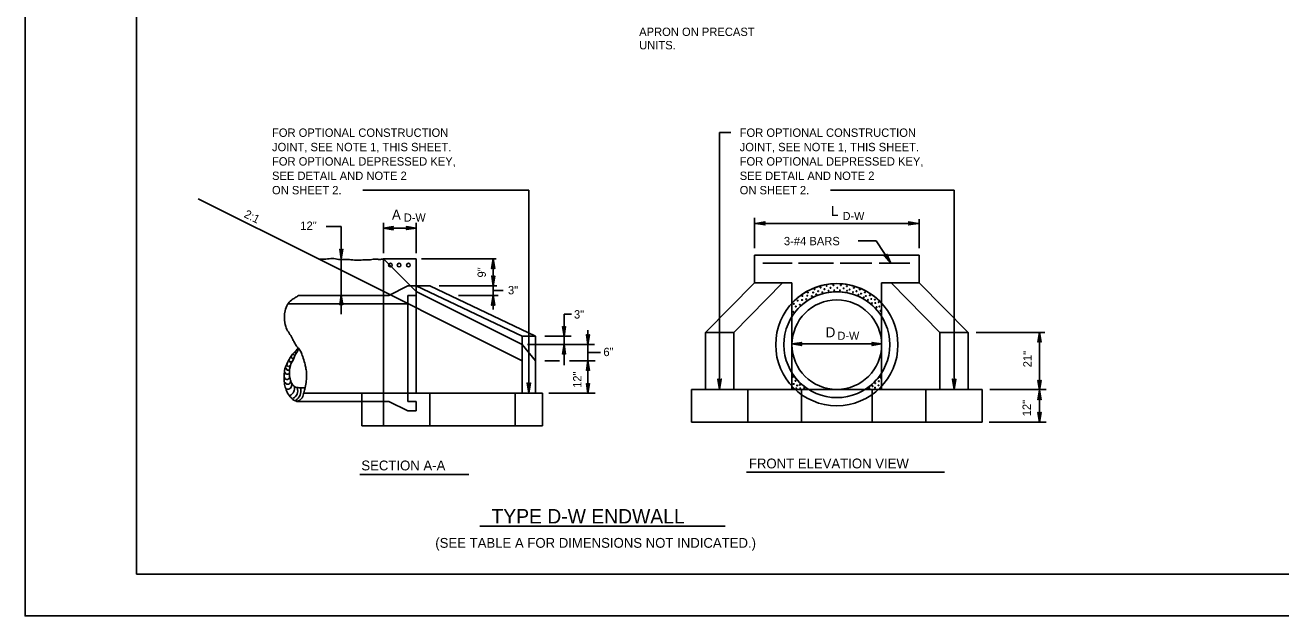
# Model space of a CAD drawing. Extents: x 638877 to 639960, y 297341 to 299123.
# Drawn here: x 638877.2 to 639328, y 297341.3 to 297553.4 of the extents above; entities that cross this region are included whole.
import ezdxf

# ---------------------------------------------------------------- set-up
doc = ezdxf.new("R2010")
doc.units = 0
for name, color, linetype in [('1', 7, 'Continuous'), ('2', 7, 'Continuous'), ('3', 7, 'Continuous'), ('PLT-BNDY', 7, 'Continuous')]:
    doc.layers.add(name, color=color, linetype=linetype)

msp = doc.modelspace()

# ---------------------------------------------------------------- linework, layer by layer
at = {"layer": '1'}
for p, q in [((638917.19, 297920.28), (638917.19, 297356.28)), ((638917.19, 297356.28), (639703.19, 297356.28))]:
    msp.add_line(p, q, dxfattribs=at)
for centre in [(639008.35, 297467.27), (639011.45, 297467.27), (639014.81, 297467.27)]:
    msp.add_circle(centre, 0.66, dxfattribs=at)
at = {"layer": '2'}
for p, q in [((639126.51, 297422.58), (639126.51, 297514.89)), ((639126.51, 297514.89), (639130.58, 297514.89)), ((639058.02, 297494.17), (638998.4, 297494.17)), ((639058.02, 297421.23), (639058.02, 297494.17)), ((639166.3, 297494.12), (639210.67, 297494.12)), ((639210.67, 297422.58), (639210.67, 297494.12)), ((638982.47, 297469.49), (638939.33, 297491.06)), ((638990.69, 297481.06), (638985.3, 297481.06)), ((638990.69, 297469.49), (638990.69, 297481.06)), ((639005.87, 297471.49), (639005.87, 297482.49)), ((639017.57, 297480.53), (639005.87, 297480.53)), ((639017.57, 297471.49), (639017.57, 297482.49)), ((639138.99, 297484.19), (639138.99, 297473.28)), ((639197.84, 297482.24), (639139.34, 297482.24)), ((639198.18, 297483.73), (639198.18, 297473.28)), ((639182.69, 297475.98), (639176.23, 297475.98)), ((639182.69, 297475.98), (639188.03, 297467.96)), ((639198.18, 297470.84), (639138.99, 297470.84)), ((639138.99, 297470.84), (639138.99, 297460.91)), ((639198.18, 297470.84), (639198.18, 297460.91)), ((639055.58, 297432.93), (638982.47, 297469.49)), ((638990.69, 297456.46), (638990.69, 297469.49)), ((639005.87, 297469.49), (639005.87, 297409.53)), ((639017.57, 297469.49), (639005.87, 297469.49)), ((639017.57, 297457.78), (639005.87, 297469.49)), ((639017.57, 297469.49), (639017.57, 297421.23)), ((639046.25, 297469.49), (639019.46, 297469.49)), ((639045.24, 297459.8), (639045.24, 297469.49)), ((639152.61, 297467.91), (639141.99, 297467.91)), ((639167.39, 297467.91), (639154.8, 297467.91)), ((639181.21, 297467.91), (639169.79, 297467.91)), ((639194.78, 297467.91), (639183.79, 297467.91)), ((639007.79, 297456.33), (639014.64, 297459.76)), ((639017.57, 297459.76), (639014.64, 297459.76)), ((639055.58, 297441.71), (639017.57, 297459.76)), ((639022.44, 297459.76), (639017.57, 297459.76)), ((639055.58, 297438.78), (639017.57, 297457.78)), ((639060.46, 297441.71), (639022.44, 297459.76)), ((639046.58, 297459.8), (639025.81, 297459.8)), ((639045.24, 297451.32), (639045.24, 297459.8)), ((639048.82, 297458.16), (639045.24, 297458.16)), ((639138.99, 297460.91), (639121.44, 297443.06)), ((639149.07, 297460.85), (639131.58, 297443.06)), ((639152.5, 297460.91), (639138.99, 297460.91)), ((639152.5, 297460.91), (639152.5, 297422.58)), ((639184.67, 297460.91), (639184.67, 297422.58)), ((639198.18, 297460.91), (639184.67, 297460.91)), ((639205.6, 297443.06), (639188.1, 297460.85)), ((639215.73, 297443.06), (639198.18, 297460.91)), ((639014.64, 297453.4), (638971.88, 297453.4)), ((639004.71, 297456.33), (638975.28, 297456.33)), ((638990.69, 297449.67), (638990.69, 297456.46)), ((639007.79, 297456.33), (639004.71, 297456.33)), ((639014.64, 297456.33), (639014.64, 297418.3)), ((639017.57, 297456.33), (639014.64, 297456.33)), ((639047.07, 297456.33), (639032.78, 297456.33)), ((639073.32, 297449.66), (639070.66, 297449.66)), ((639070.66, 297441.71), (639070.66, 297449.66)), ((639079.24, 297441.71), (639079.24, 297443.86)), ((639055.58, 297441.71), (639055.58, 297421.23)), ((639060.46, 297441.71), (639055.58, 297441.71)), ((639060.46, 297441.71), (639060.46, 297421.23)), ((639073.27, 297441.71), (639063.78, 297441.71)), ((639070.66, 297431.32), (639070.66, 297441.71)), ((639079.24, 297432.93), (639079.24, 297441.71)), ((639131.58, 297443.06), (639121.44, 297443.06)), ((639121.44, 297422.58), (639121.44, 297443.06)), ((639131.58, 297422.58), (639131.58, 297443.06)), ((639215.73, 297443.06), (639205.6, 297443.06)), ((639205.6, 297422.58), (639205.6, 297443.06)), ((639215.73, 297422.58), (639215.73, 297443.06)), ((639243.3, 297443.06), (639218.63, 297443.06)), ((639241.36, 297443.06), (639241.36, 297422.37)), ((639055.58, 297438.78), (639060.46, 297432.93)), ((639081.55, 297438.78), (639057.51, 297438.78)), ((639083.74, 297435.84), (639079.43, 297435.84)), ((639184.67, 297438.95), (639152.5, 297438.95)), ((639069.07, 297432.93), (639063.73, 297432.93)), ((639081.78, 297432.93), (639072.59, 297432.93)), ((639079.24, 297421.23), (639079.24, 297432.93)), ((638998.07, 297421.23), (638977.24, 297421.23)), ((638998.07, 297421.23), (638998.07, 297409.53)), ((639055.58, 297421.23), (638998.07, 297421.23)), ((639022.45, 297421.23), (639022.45, 297409.53)), ((639053.15, 297421.23), (639053.15, 297409.53)), ((639055.58, 297421.23), (639060.46, 297421.23)), ((639062.9, 297421.23), (639060.46, 297421.23)), ((639062.9, 297421.23), (639062.9, 297409.53)), ((639081.78, 297421.23), (639065.15, 297421.23)), ((639116.38, 297410.88), (639116.38, 297422.58)), ((639121.44, 297422.58), (639116.38, 297422.58)), ((639131.58, 297422.58), (639121.44, 297422.58)), ((639205.6, 297422.58), (639131.58, 297422.58)), ((639136.64, 297410.88), (639136.64, 297422.58)), ((639155.88, 297410.88), (639155.88, 297422.58)), ((639168.59, 297422.58), (639168.59, 297422.58)), ((639181.3, 297410.88), (639181.3, 297422.58)), ((639200.54, 297410.88), (639200.54, 297422.58)), ((639215.74, 297422.58), (639205.6, 297422.58)), ((639220.8, 297422.58), (639215.73, 297422.58)), ((639220.8, 297410.88), (639220.8, 297422.58)), ((639243.73, 297422.58), (639223.54, 297422.58)), ((639241.36, 297422.37), (639241.36, 297410.88)), ((638998.07, 297418.3), (638974.56, 297418.3)), ((639007.79, 297418.3), (638998.07, 297418.3)), ((639014.64, 297414.88), (639007.79, 297418.3)), ((639017.57, 297418.3), (639014.64, 297418.3)), ((639017.57, 297418.3), (639017.57, 297414.88)), ((639017.57, 297414.88), (639014.64, 297414.88)), ((639062.9, 297409.53), (638998.07, 297409.53)), ((639220.8, 297410.88), (639116.38, 297410.88)), ((639243.73, 297410.88), (639223.32, 297410.88))]:
    msp.add_line(p, q, dxfattribs=at)
for points in [[(639009.17, 297480.11), (639009.05, 297480.35), (639005.87, 297480.53), (639009.17, 297480.11), (639009.35, 297479.97), (639005.87, 297480.53), (639009.05, 297480.69), (639009.17, 297480.93), (639005.87, 297480.53), (639009.35, 297481.08), (639009.17, 297480.93)], [(639014.27, 297480.95), (639014.39, 297480.71), (639017.57, 297480.53), (639014.27, 297480.95), (639014.09, 297481.09), (639017.57, 297480.53), (639014.39, 297480.37), (639014.27, 297480.14), (639017.57, 297480.53), (639014.09, 297479.98), (639014.27, 297480.14)], [(639142.64, 297481.82), (639142.52, 297482.06), (639139.34, 297482.24), (639142.64, 297481.82), (639142.81, 297481.68), (639139.34, 297482.24), (639142.52, 297482.39), (639142.63, 297482.63), (639139.34, 297482.24), (639142.81, 297482.79), (639142.63, 297482.63)], [(639194.53, 297482.65), (639194.65, 297482.41), (639197.84, 297482.24), (639194.53, 297482.65), (639194.36, 297482.79), (639197.84, 297482.24), (639194.66, 297482.08), (639194.54, 297481.84), (639197.84, 297482.24), (639194.36, 297481.68), (639194.54, 297481.84)], [(638991.11, 297472.79), (638990.87, 297472.67), (638990.69, 297469.49), (638991.11, 297472.79), (638991.25, 297472.96), (638990.69, 297469.49), (638990.54, 297472.67), (638990.3, 297472.78), (638990.69, 297469.49), (638990.14, 297472.96), (638990.3, 297472.78)], [(639186.54, 297470.94), (639186.41, 297470.7), (639188.03, 297467.96), (639186.54, 297470.94), (639186.56, 297471.16), (639188.03, 297467.96), (639186.13, 297470.51), (639185.87, 297470.48), (639188.03, 297467.96), (639185.64, 297470.54), (639185.87, 297470.48)], [(639044.82, 297466.18), (639045.06, 297466.31), (639045.24, 297469.49), (639044.82, 297466.18), (639044.68, 297466.01), (639045.24, 297469.49), (639045.4, 297466.31), (639045.63, 297466.19), (639045.24, 297469.49), (639045.79, 297466.01), (639045.63, 297466.19)], [(639045.66, 297463.11), (639045.42, 297462.99), (639045.24, 297459.8), (639045.66, 297463.11), (639045.8, 297463.28), (639045.24, 297459.8), (639045.08, 297462.98), (639044.84, 297463.1), (639045.24, 297459.8), (639044.69, 297463.28), (639044.84, 297463.1)], [(638990.28, 297453.16), (638990.52, 297453.28), (638990.69, 297456.46), (638990.28, 297453.16), (638990.13, 297452.99), (638990.69, 297456.46), (638990.85, 297453.28), (638991.09, 297453.17), (638990.69, 297456.46), (638991.24, 297452.99), (638991.09, 297453.17)], [(639044.82, 297453.02), (639045.06, 297453.15), (639045.24, 297456.33), (639044.82, 297453.02), (639044.68, 297452.85), (639045.24, 297456.33), (639045.4, 297453.15), (639045.63, 297453.03), (639045.24, 297456.33), (639045.79, 297452.85), (639045.63, 297453.03)], [(639071.08, 297445.01), (639070.84, 297444.89), (639070.66, 297441.71), (639071.08, 297445.01), (639071.22, 297445.18), (639070.66, 297441.71), (639070.5, 297444.89), (639070.26, 297445), (639070.66, 297441.71), (639070.11, 297445.18), (639070.26, 297445)], [(639079.66, 297442.08), (639079.42, 297441.96), (639079.24, 297438.78), (639079.66, 297442.08), (639079.8, 297442.26), (639079.24, 297438.78), (639079.08, 297441.96), (639078.84, 297442.08), (639079.24, 297438.78), (639078.69, 297442.26), (639078.84, 297442.08)], [(639155.81, 297438.53), (639155.68, 297438.77), (639152.5, 297438.95), (639155.81, 297438.53), (639155.98, 297438.39), (639152.5, 297438.95), (639155.68, 297439.11), (639155.8, 297439.35), (639152.5, 297438.95), (639155.98, 297439.5), (639155.8, 297439.35)], [(639181.37, 297439.37), (639181.49, 297439.13), (639184.67, 297438.95), (639181.37, 297439.37), (639181.2, 297439.51), (639184.67, 297438.95), (639181.49, 297438.79), (639181.38, 297438.56), (639184.67, 297438.95), (639181.2, 297438.4), (639181.38, 297438.56)], [(639240.94, 297439.76), (639241.18, 297439.88), (639241.36, 297443.06), (639240.94, 297439.76), (639240.8, 297439.59), (639241.36, 297443.06), (639241.51, 297439.88), (639241.75, 297439.76), (639241.36, 297443.06), (639241.91, 297439.59), (639241.75, 297439.76)], [(639070.24, 297435.47), (639070.48, 297435.6), (639070.66, 297438.78), (639070.24, 297435.47), (639070.1, 297435.3), (639070.66, 297438.78), (639070.82, 297435.6), (639071.05, 297435.48), (639070.66, 297438.78), (639071.21, 297435.3), (639071.05, 297435.48)], [(639078.82, 297429.62), (639079.06, 297429.75), (639079.24, 297432.93), (639078.82, 297429.62), (639078.68, 297429.45), (639079.24, 297432.93), (639079.4, 297429.75), (639079.63, 297429.63), (639079.24, 297432.93), (639079.79, 297429.45), (639079.63, 297429.63)], [(639126.06, 297426.13), (639126.32, 297425.99), (639126.51, 297422.58), (639126.06, 297426.13), (639125.91, 297426.31), (639126.51, 297422.58), (639126.68, 297425.99), (639126.93, 297426.11), (639126.51, 297422.58), (639127.1, 297426.31), (639126.93, 297426.11)], [(639210.23, 297426.13), (639210.48, 297425.99), (639210.67, 297422.58), (639210.23, 297426.13), (639210.07, 297426.31), (639210.67, 297422.58), (639210.84, 297425.99), (639211.09, 297426.11), (639210.67, 297422.58), (639211.26, 297426.31), (639211.09, 297426.11)], [(639241.77, 297425.68), (639241.54, 297425.56), (639241.36, 297422.37), (639241.77, 297425.68), (639241.92, 297425.85), (639241.36, 297422.37), (639241.2, 297425.55), (639240.96, 297425.67), (639241.36, 297422.37), (639240.81, 297425.85), (639240.96, 297425.67)], [(639057.58, 297424.77), (639057.84, 297424.64), (639058.02, 297421.23), (639057.58, 297424.77), (639057.42, 297424.95), (639058.02, 297421.23), (639058.19, 297424.64), (639058.44, 297424.76), (639058.02, 297421.23), (639058.62, 297424.95), (639058.44, 297424.76)], [(639079.66, 297424.53), (639079.42, 297424.41), (639079.24, 297421.23), (639079.66, 297424.53), (639079.8, 297424.71), (639079.24, 297421.23), (639079.08, 297424.41), (639078.84, 297424.53), (639079.24, 297421.23), (639078.69, 297424.71), (639078.84, 297424.53)], [(639240.94, 297419.07), (639241.18, 297419.19), (639241.36, 297422.37), (639240.94, 297419.07), (639240.8, 297418.9), (639241.36, 297422.37), (639241.51, 297419.19), (639241.75, 297419.08), (639241.36, 297422.37), (639241.91, 297418.9), (639241.75, 297419.08)], [(639241.77, 297414.19), (639241.54, 297414.07), (639241.36, 297410.88), (639241.77, 297414.19), (639241.92, 297414.36), (639241.36, 297410.88), (639241.2, 297414.06), (639240.96, 297414.18), (639241.36, 297410.88), (639240.81, 297414.36), (639240.96, 297414.18)]]:
    msp.add_lwpolyline(points, dxfattribs=at)
for centre, radius in [((639168.59, 297438.67), 21.94), ((639168.59, 297438.67), 19.01), ((639158.17, 297457.41), 0.133), ((639160.07, 297457.41), 0.133), ((639160.6, 297458.61), 0.133), ((639161.91, 297457.86), 0.133), ((639162.76, 297459.2), 0.133), ((639163.4, 297457.49), 0.133), ((639164.14, 297458.61), 0.133), ((639164.95, 297459.84), 0.133), ((639165.58, 297458), 0.133), ((639166.33, 297459.09), 0.133), ((639167.37, 297460.05), 0.133), ((639167.69, 297458.21), 0.133), ((639168.79, 297459.09), 0.133), ((639169.72, 297458.16), 0.133), ((639170.01, 297460.05), 0.133), ((639171.03, 297458.9), 0.133), ((639172.17, 297459.7), 0.133), ((639172.31, 297458.05), 0.133), ((639173.21, 297458.5), 0.133), ((639174.41, 297457.54), 0.133), ((639174.71, 297459.09), 0.133), ((639175.64, 297457.86), 0.133), ((639176.84, 297458.5), 0.133), ((639178.68, 297457.46), 0.133), ((639168.59, 297438.67), 16.09), ((639153.13, 297453.35), 0.133), ((639154.54, 297454.5), 0.133), ((639155.29, 297453.06), 0.133), ((639156.12, 297454.71), 0.133), ((639156.22, 297456.15), 0.133), ((639157.58, 297455.01), 0.133), ((639157.99, 297456.26), 0.133), ((639159.61, 297456.1), 0.133), ((639161.21, 297456.74), 0.133), ((639176.39, 297456.61), 0.133), ((639177.3, 297457.01), 0.133), ((639178.28, 297455.7), 0.133), ((639179.03, 297456.15), 0.133), ((639179.78, 297454.77), 0.133), ((639180.47, 297456.4), 0.133), ((639180.98, 297455.06), 0.133), ((639181.22, 297453.57), 0.133), ((639182.23, 297454.85), 0.133), ((639182.42, 297453.62), 0.133), ((639183.62, 297453.92), 0.133), ((639153, 297450.47), 0.133), ((639153.85, 297452.37), 0.133), ((639182.87, 297452.13), 0.133), ((639183.86, 297452.37), 0.133), ((639184.26, 297450.82), 0.133), ((639152.84, 297427.14), 0.133), ((639153.74, 297425.72), 0.133), ((639183.67, 297425.59), 0.133), ((639184.26, 297426.92), 0.133), ((639152.94, 297423.08), 0.133), ((639153.13, 297424.58), 0.133), ((639154.04, 297423), 0.133), ((639154.33, 297424.04), 0.133), ((639155.29, 297424.28), 0.133), ((639155.48, 297423), 0.133), ((639156.86, 297423.13), 0.133), ((639180.23, 297423.08), 0.133), ((639181.43, 297423.77), 0.133), ((639182.31, 297423.24), 0.133), ((639182.36, 297424.84), 0.133), ((639183.56, 297424.09), 0.133), ((639184.31, 297422.95), 0.133)]:
    msp.add_circle(centre, radius, dxfattribs=at)
for centre, radius, start, end in [((639168.59, 297438.67), 21.94, 42.9224, 137.3086), ((639168.59, 297438.67), 19.01, 32.7824, 147.983), ((638974.14, 297435.62), 0.723, 214.194, 254.3926), ((638974.39, 297435.95), 0.307, 86.947, 3.053), ((638971.59, 297430.22), 0.707, 177.6701, 316.2915), ((638971.77, 297431.44), 0.614, 127.1633, 351.4543), ((638972.4, 297432.84), 0.423, 136.1947, 336.6659), ((638973.19, 297434.12), 0.419, 146.1449, 344.2438), ((638971.16, 297427.07), 0.87, 191.4984, 340.2996), ((638971.28, 297428.81), 0.763, 193.3175, 327.589), ((639168.59, 297438.67), 19.01, 212.5031, 238.1278), ((639168.59, 297438.67), 19.01, 302.196, 327.9127), ((638971.45, 297425.47), 1.01, 204.5127, 8.9205), ((638971.35, 297424.28), 1.62, 261.4216, 6.7911), ((638971, 297422.97), 2.87, 297.4769, 15.1492), ((638972.2, 297422.05), 2.86, 294.0664, 21.1035), ((638972.18, 297422.11), 4.04, 302.4871, 11.509)]:
    msp.add_arc(centre, radius, start, end, dxfattribs=at)
for points in [[(638982.47, 297469.49), (638985.2, 297469.41), (638987.52, 297469.63), (638989.74, 297469.29), (638991.96, 297469.29), (638994.18, 297469.19), (638996.72, 297468.98), (638999.03, 297469.19), (639001.16, 297469.19), (639003.04, 297469.41), (639004.47, 297469.29), (639005.87, 297469.49)], [(638975.28, 297456.33), (638974.06, 297455.49), (638972.79, 297454.68), (638971.4, 297453.12), (638970.53, 297450.81), (638970.48, 297446.48), (638971.17, 297444.11), (638972.27, 297442.38), (638973.25, 297440.53), (638974, 297439.26), (638974.64, 297438.16), (638975.28, 297437.41), (638976.25, 297435.96), (638976.83, 297434.46), (638977.58, 297431.98), (638977.93, 297430.48), (638978.22, 297428.69), (638978.22, 297427.36), (638978.04, 297425.11), (638977.58, 297422.73), (638977.18, 297421), (638976.31, 297419.21), (638975.28, 297418.49), (638973.94, 297418.58), (638972.67, 297419.68), (638971.63, 297420.94), (638970.93, 297422.45), (638970.36, 297424.41), (638970.18, 297426.78), (638970.25, 297428.75), (638970.88, 297431.17), (638971.8, 297432.96), (638972.67, 297434.58), (638973.77, 297435.85), (638975.28, 297437.41)], [(638977.75, 297423.22), (638976.6, 297423.14), (638975.1, 297423.26), (638974.29, 297423.37), (638973.65, 297423.95), (638973.19, 297424.41), (638972.73, 297425.16), (638972.38, 297426.2), (638972.15, 297427.3), (638972.09, 297428.51), (638972.09, 297429.55), (638972.32, 297430.65), (638972.56, 297431.69), (638972.96, 297432.44), (638973.71, 297433.77), (638973.94, 297434.41), (638974.17, 297434.98), (638974.81, 297435.96), (638975.1, 297436.66), (638975.28, 297437.41)]]:
    msp.add_spline(points, degree=3, dxfattribs=at)
at = {"layer": '3'}
for p, q in [((638997.4, 297392.1), (639036.47, 297392.1)), ((639136.13, 297392.89), (639207.28, 297392.89)), ((639040.49, 297373.5), (639128.5, 297373.5))]:
    msp.add_line(p, q, dxfattribs=at)
at = {"layer": 'PLT-BNDY'}
msp.add_lwpolyline([(638877.19, 297935.28), (639718.19, 297935.28), (639718.19, 297341.28), (638877.19, 297341.28)], close=True, dxfattribs=at)

# ---------------------------------------------------------------- texts
at = {"layer": '1'}
for s, height, p in [('APRON ON PRECAST', 2.9999, (639097.63, 297549.53)), ('UNITS.', 3, (639097.63, 297544.73)), ('D-W', 2.916, (639013.18, 297482.87)), ('D-W', 2.916, (639170.68, 297483.43)), ('D-W', 2.916, (639168.85, 297440.42)), ('(SEE TABLE A FOR DIMENSIONS NOT INDICATED.)', 3.53, (639024.44, 297365.74))]:
    msp.add_text(s, height=height, dxfattribs=at).set_placement(p)
at = {"layer": '2'}
msp.add_text('D', height=3.6, dxfattribs=at).set_placement((639164.57, 297441.33))
at = {"layer": '3'}
for s, height, p in [('FOR OPTIONAL CONSTRUCTION', 2.9999, (638965.82, 297513.31)), ('FOR OPTIONAL CONSTRUCTION', 2.9999, (639133.72, 297513.31)), ('JOINT, SEE NOTE 1, THIS SHEET.', 2.9999, (638965.82, 297508.15)), ('JOINT, SEE NOTE 1, THIS SHEET.', 2.9999, (639133.72, 297508.15)), ('FOR OPTIONAL DEPRESSED KEY,', 2.9999, (638965.82, 297502.99)), ('FOR OPTIONAL DEPRESSED KEY,', 2.9999, (639133.72, 297502.99)), ('SEE DETAIL AND NOTE 2 ', 2.9999, (638965.82, 297497.83)), ('SEE DETAIL AND NOTE 2 ', 2.9999, (639133.72, 297497.83)), ('ON SHEET 2.', 2.9999, (638965.82, 297492.67)), ('ON SHEET 2.', 2.9999, (639133.72, 297492.67)), ('A', 3.6, (639008.87, 297483.54)), ('L', 3.6, (639166.51, 297484.92)), ('12"', 3, (638975.98, 297479.9)), ('3-#4 BARS', 3, (639149.59, 297474.38)), ('3"', 3, (639050.54, 297456.75)), ('3"', 3, (639074.23, 297448.06)), ('6"', 3, (639084.8, 297434.56)), ('SECTION A-A', 3.5299, (638997.9, 297393.53)), ('FRONT ELEVATION VIEW', 3.5299, (639137.02, 297394.25)), ('TYPE D-W ENDWALL', 5.186, (639044.62, 297374.47))]:
    msp.add_text(s, height=height, dxfattribs=at).set_placement(p)
for s, rotation, p in [('2:1', 333.435, (638955.52, 297484.6)), ('9"', 90, (639042.61, 297462.8)), ('21"', 90, (639238.52, 297430.55)), ('12"', 90, (639076.92, 297423.16)), ('12"', 90, (639238.26, 297412.96))]:
    msp.add_text(s, height=3, rotation=rotation, dxfattribs=at).set_placement(p)

doc.saveas('drawing.dxf')
